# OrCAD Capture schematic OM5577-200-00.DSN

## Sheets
1 PN7120: size A4; title: .; rev: 00; note: PN7120 NFC Controller Board
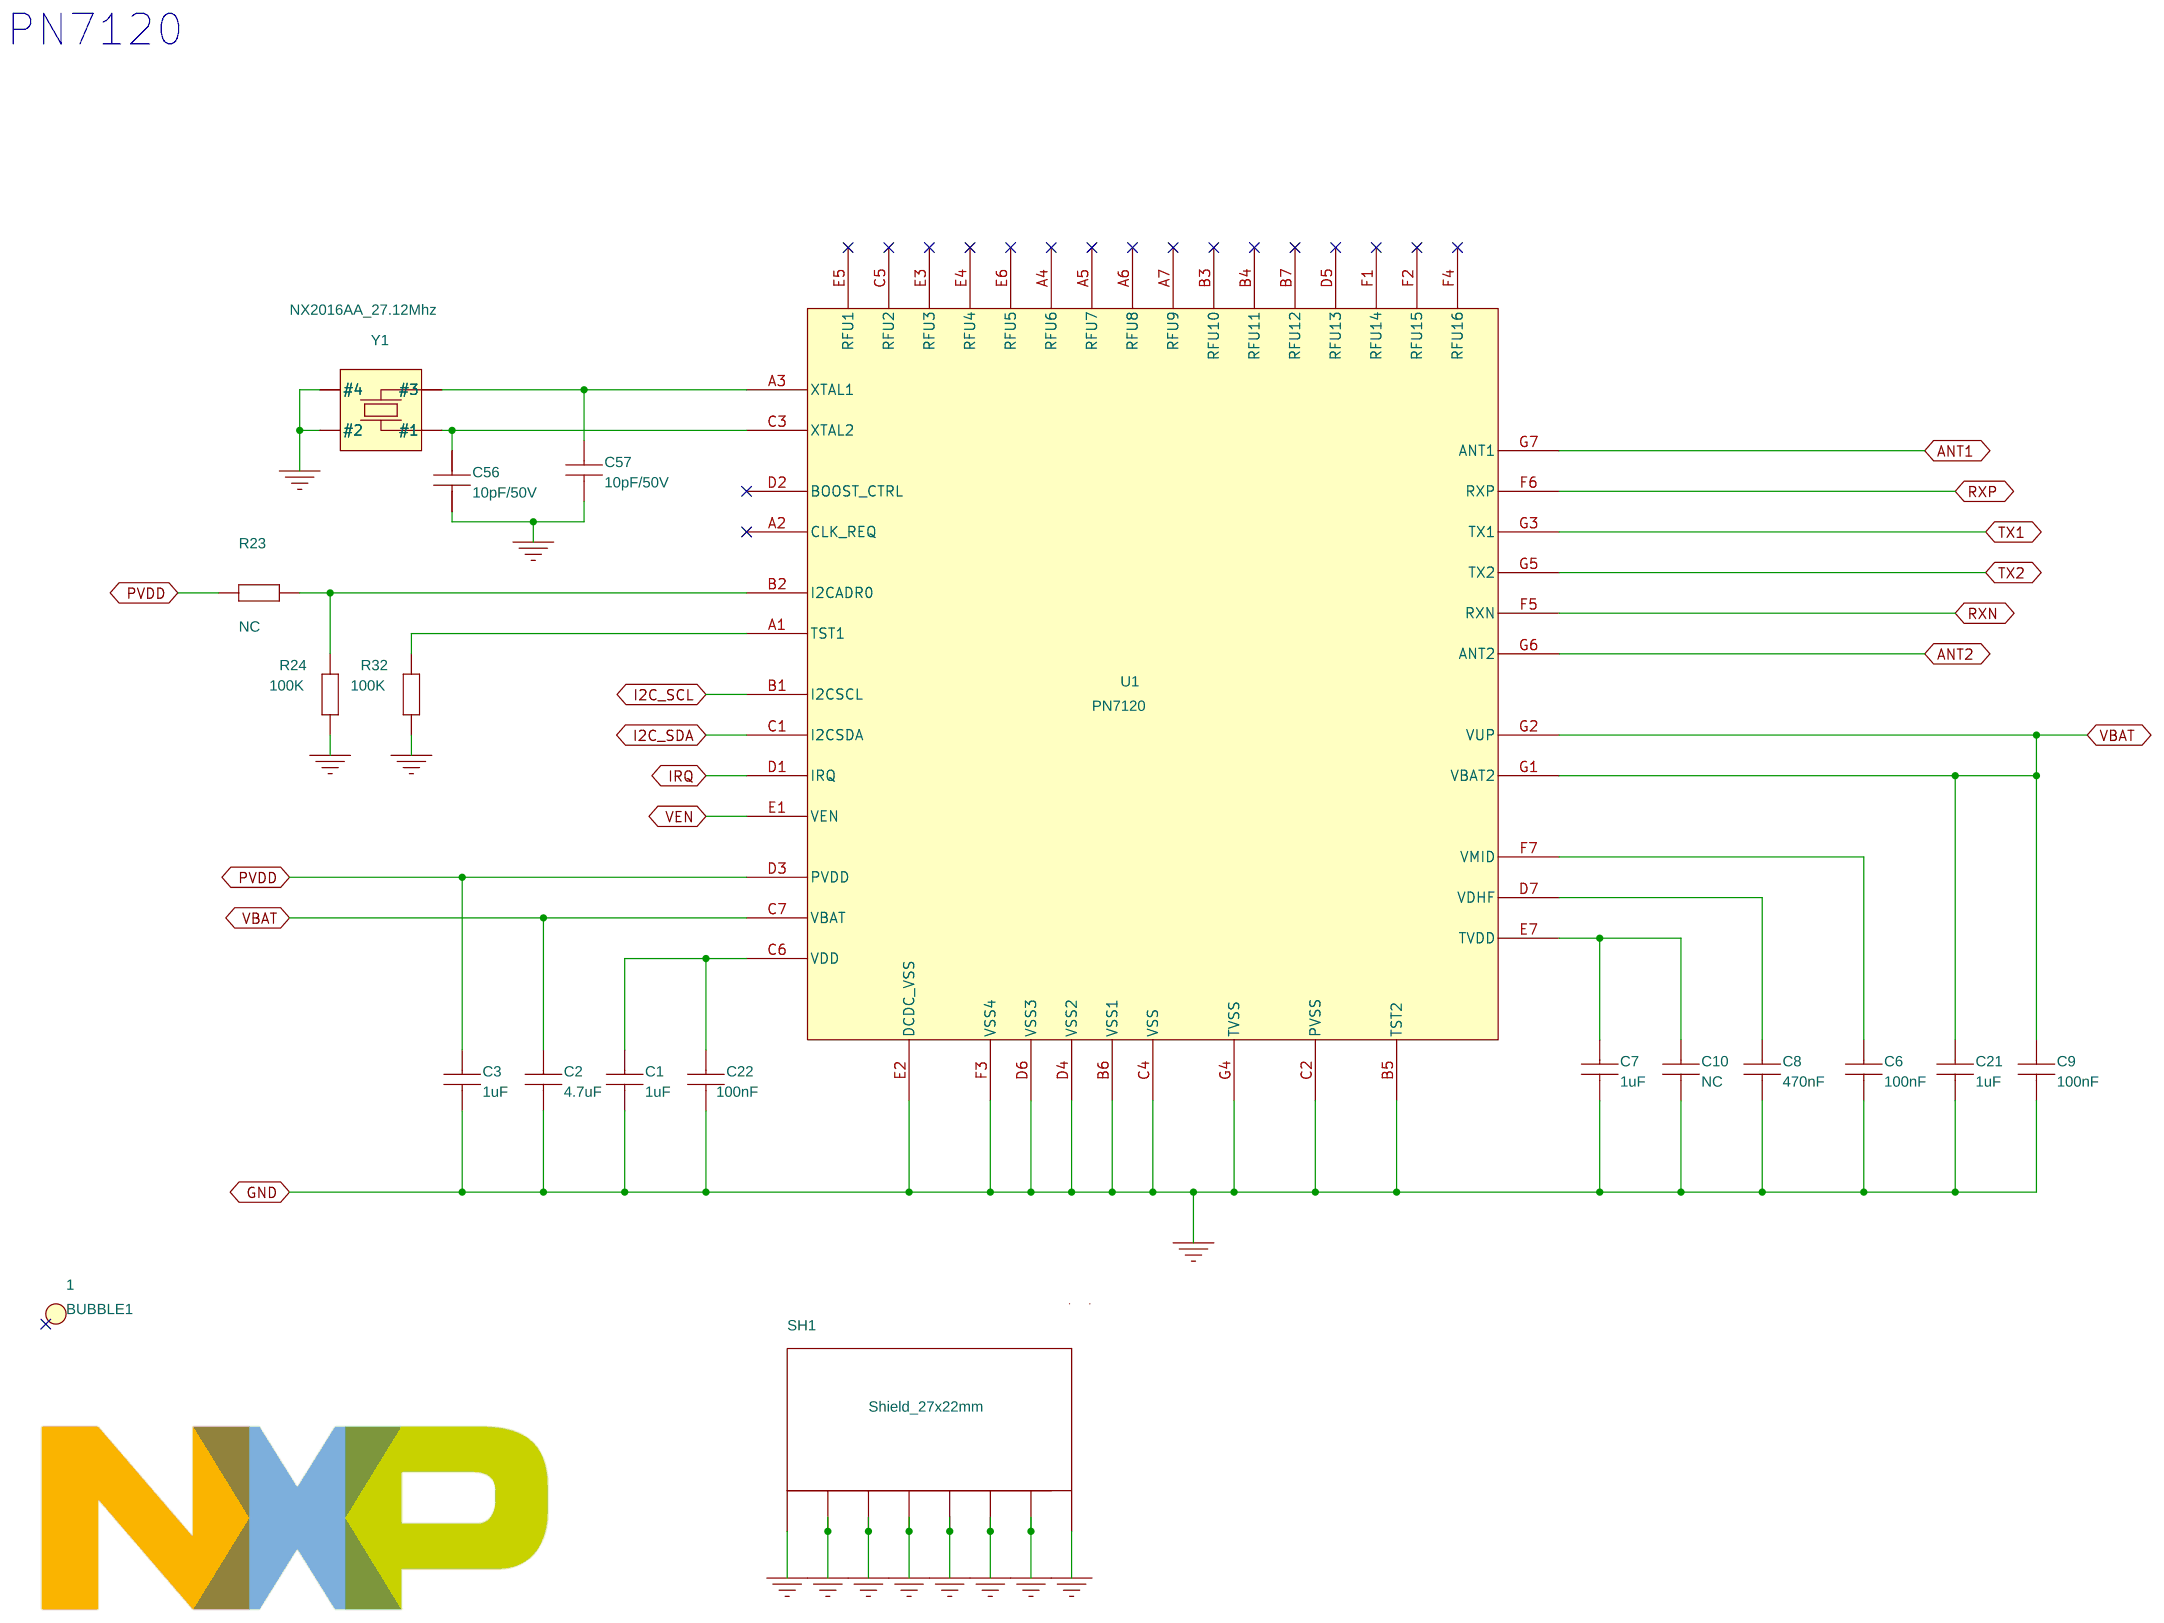
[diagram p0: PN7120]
2 RF Interface: size A4
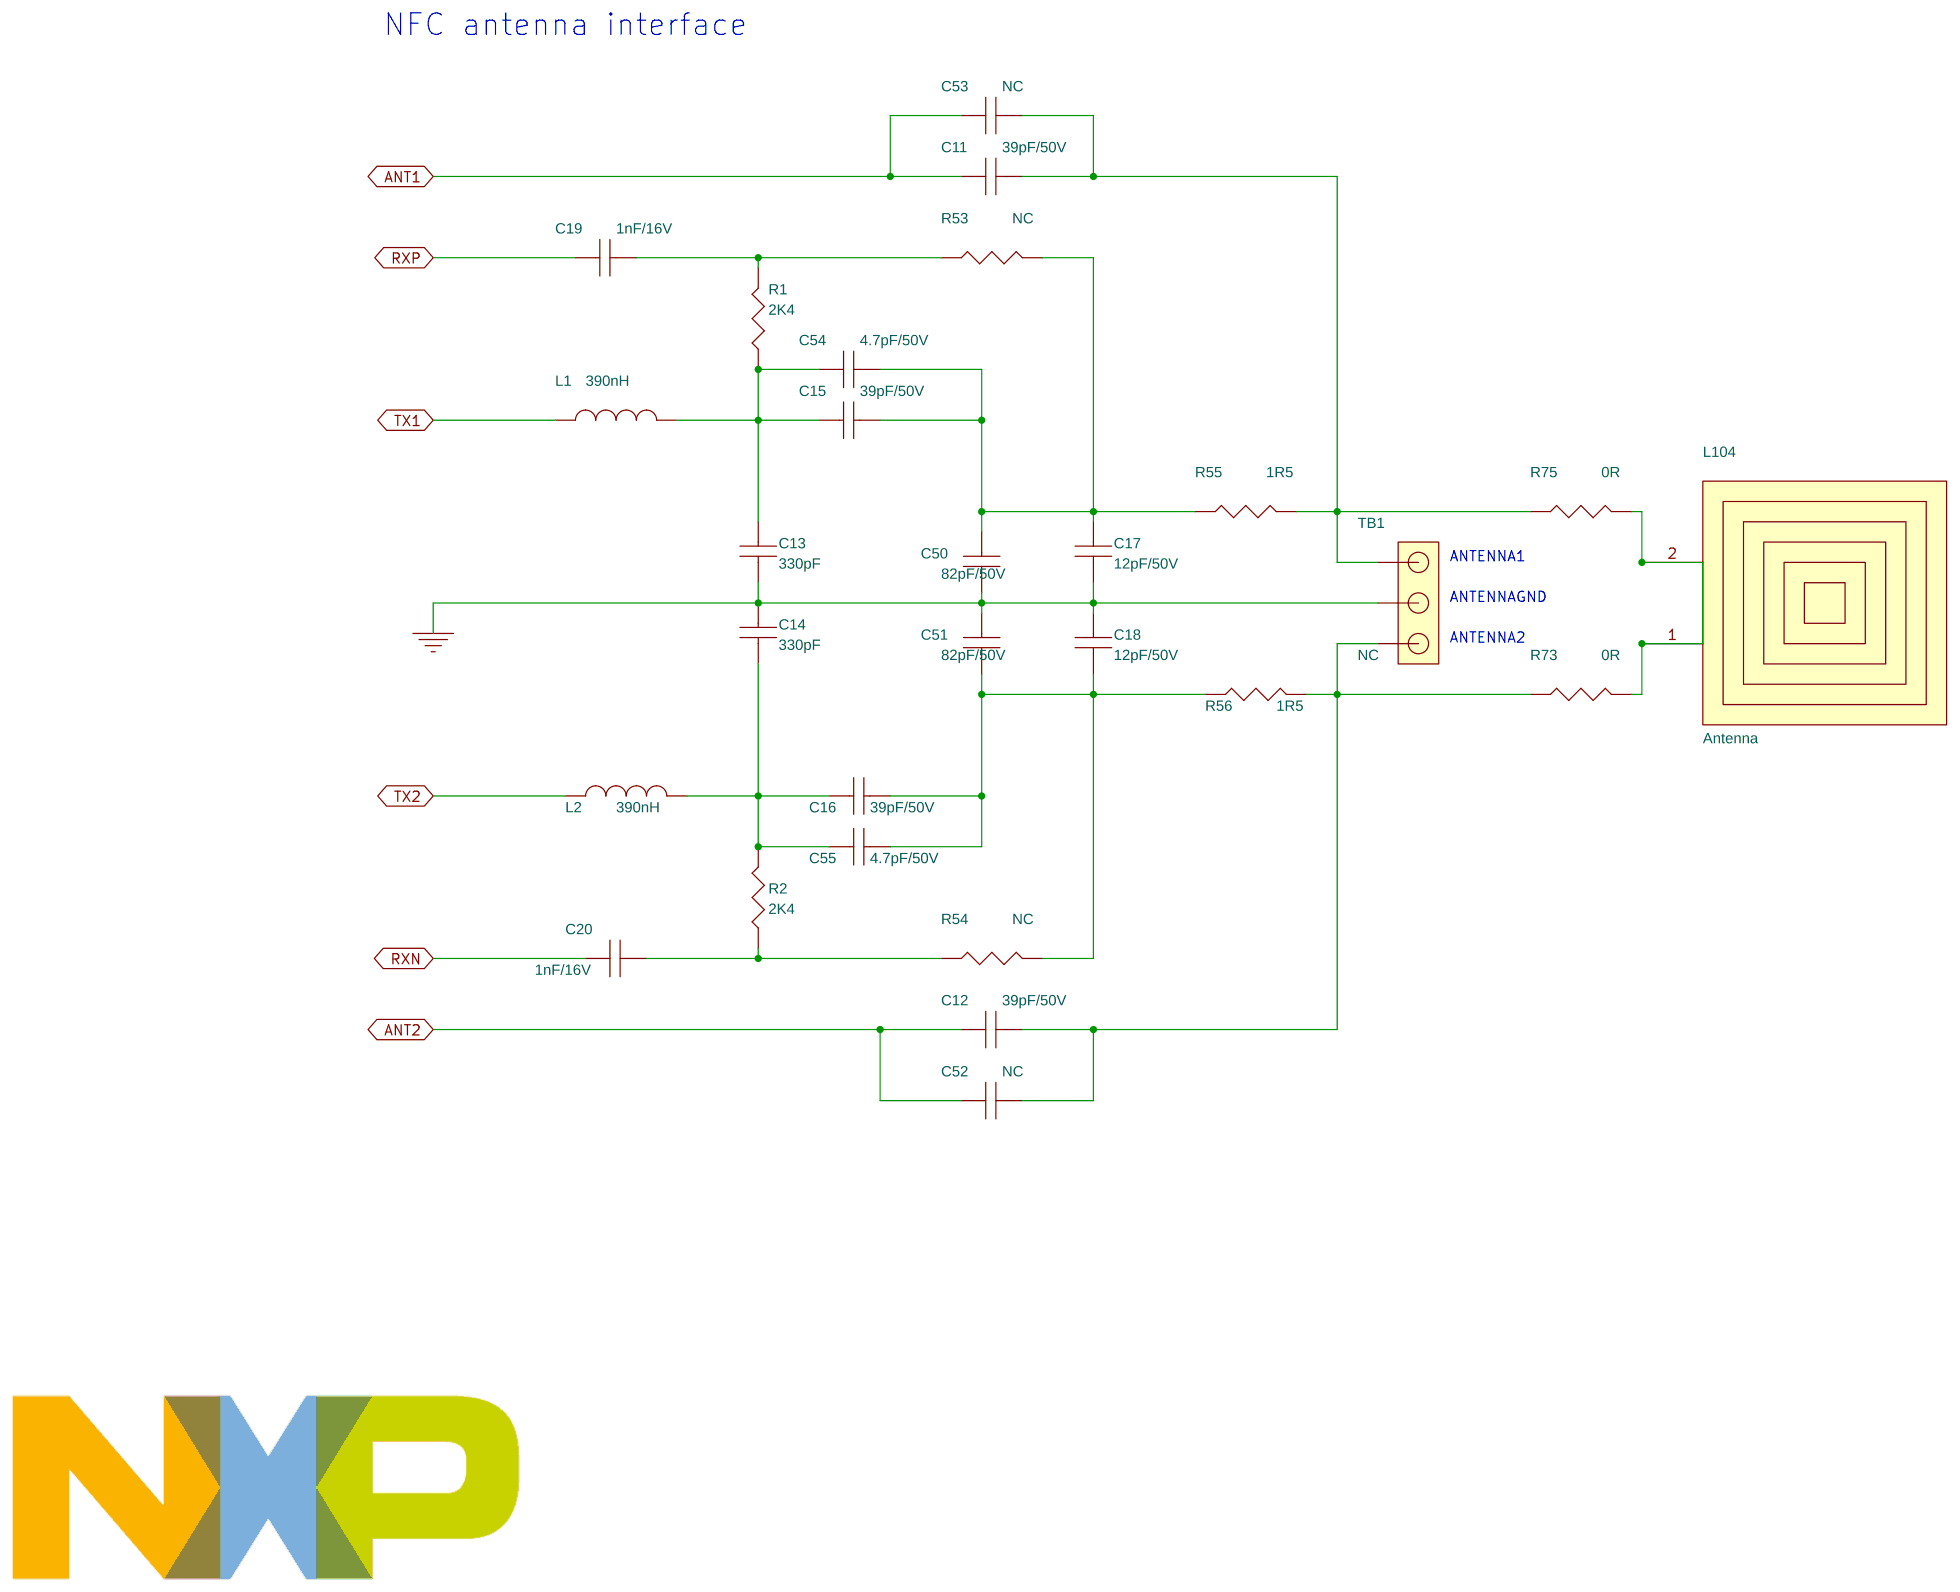
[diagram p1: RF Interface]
3 Connectors: size A4
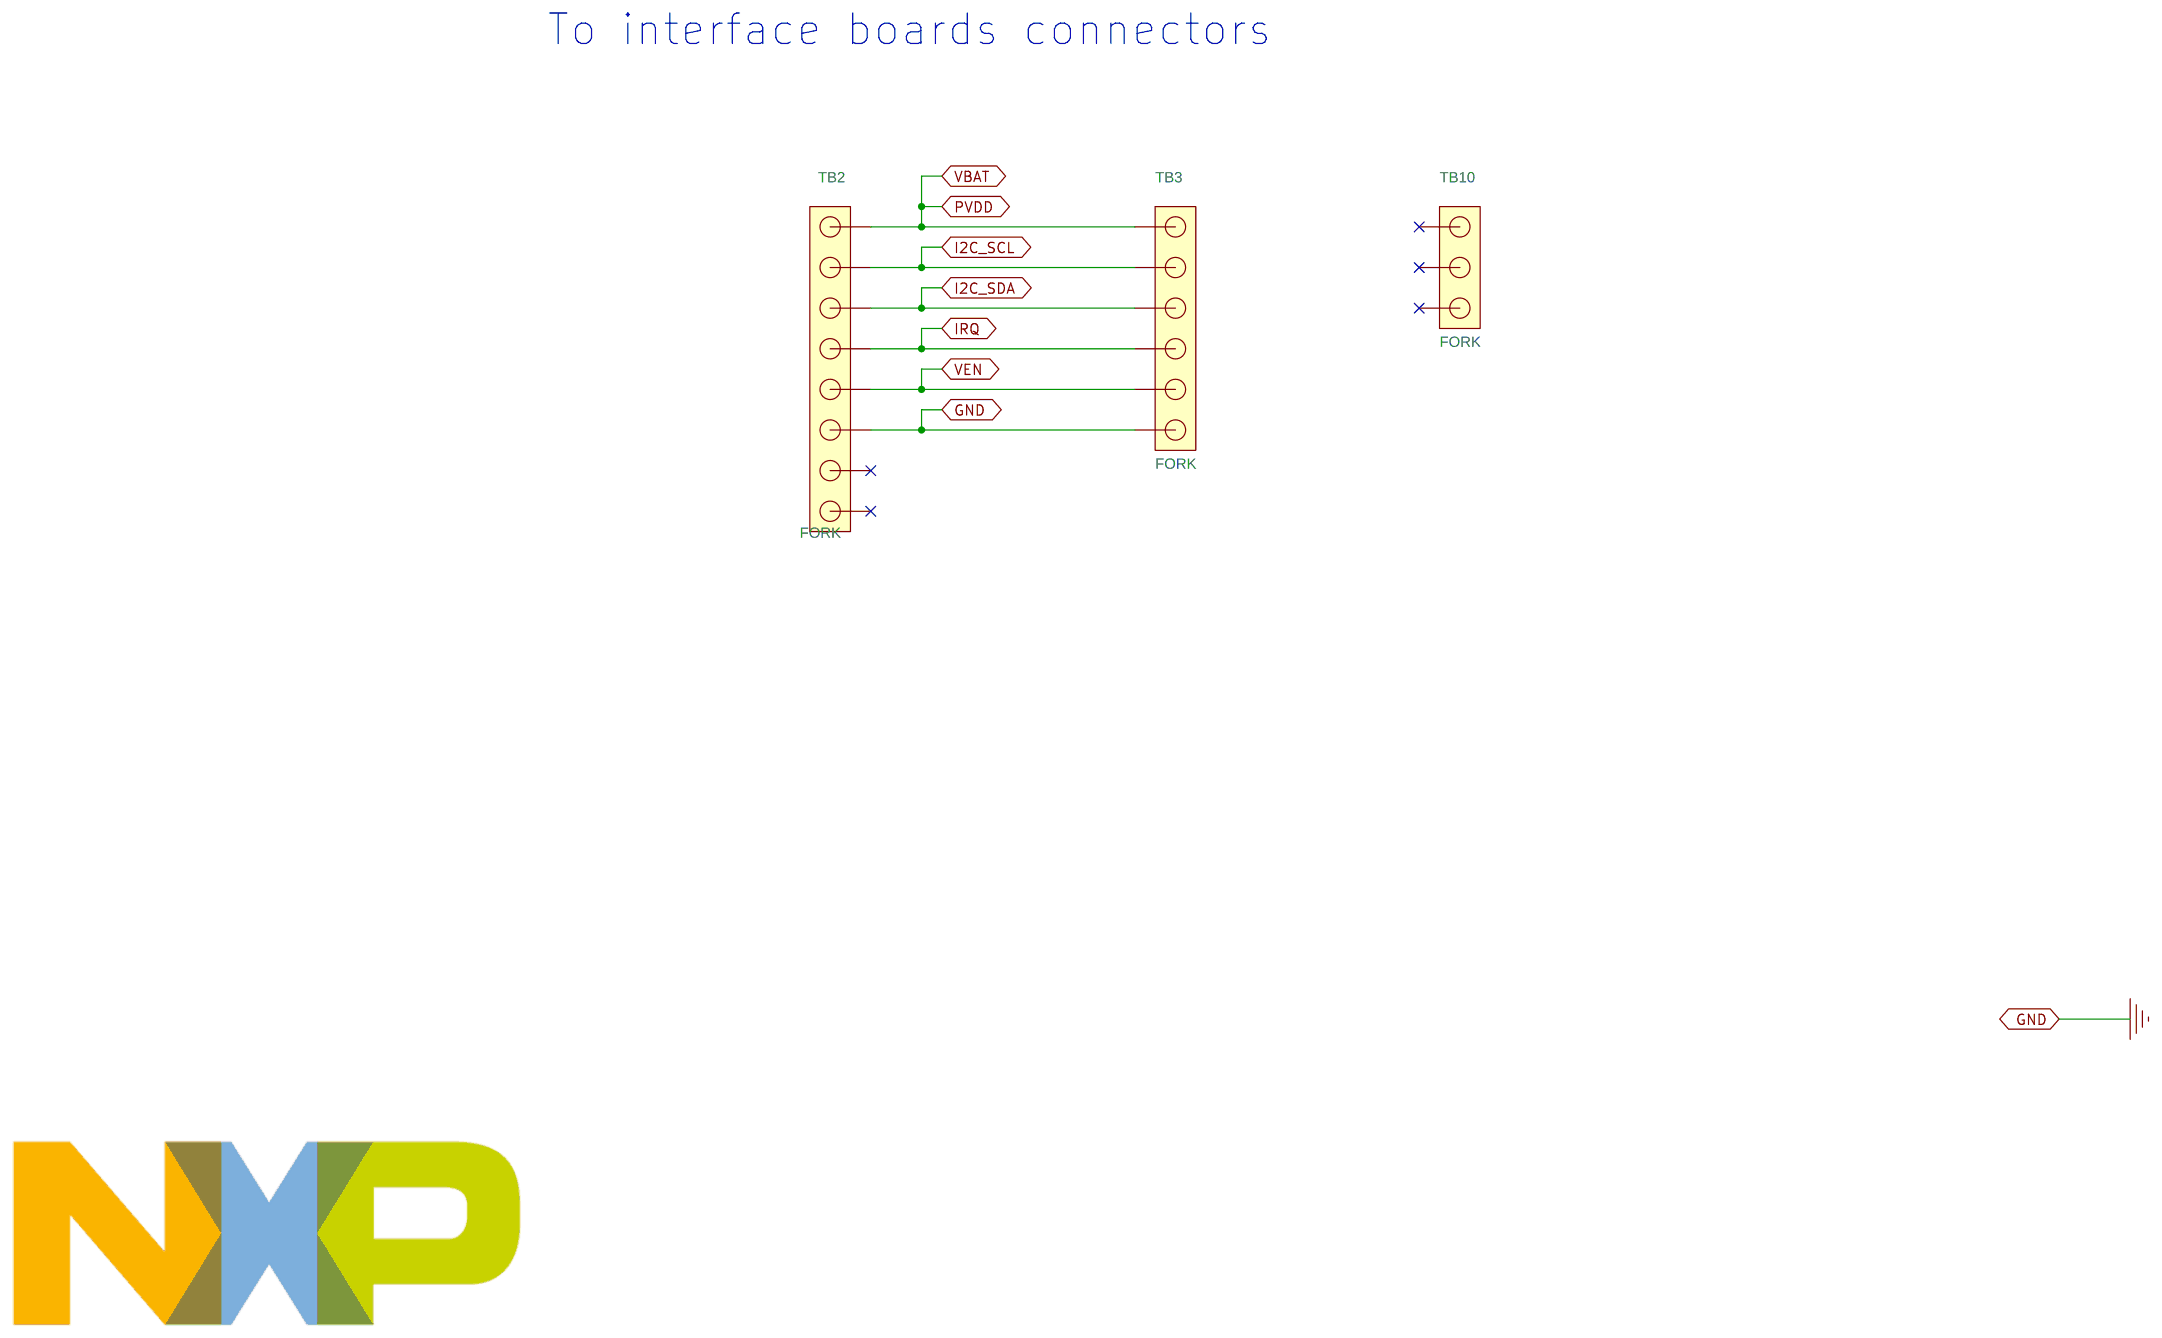
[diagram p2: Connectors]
4 BEAGLEBONE: size A4; note: BeagleBone Interface Board
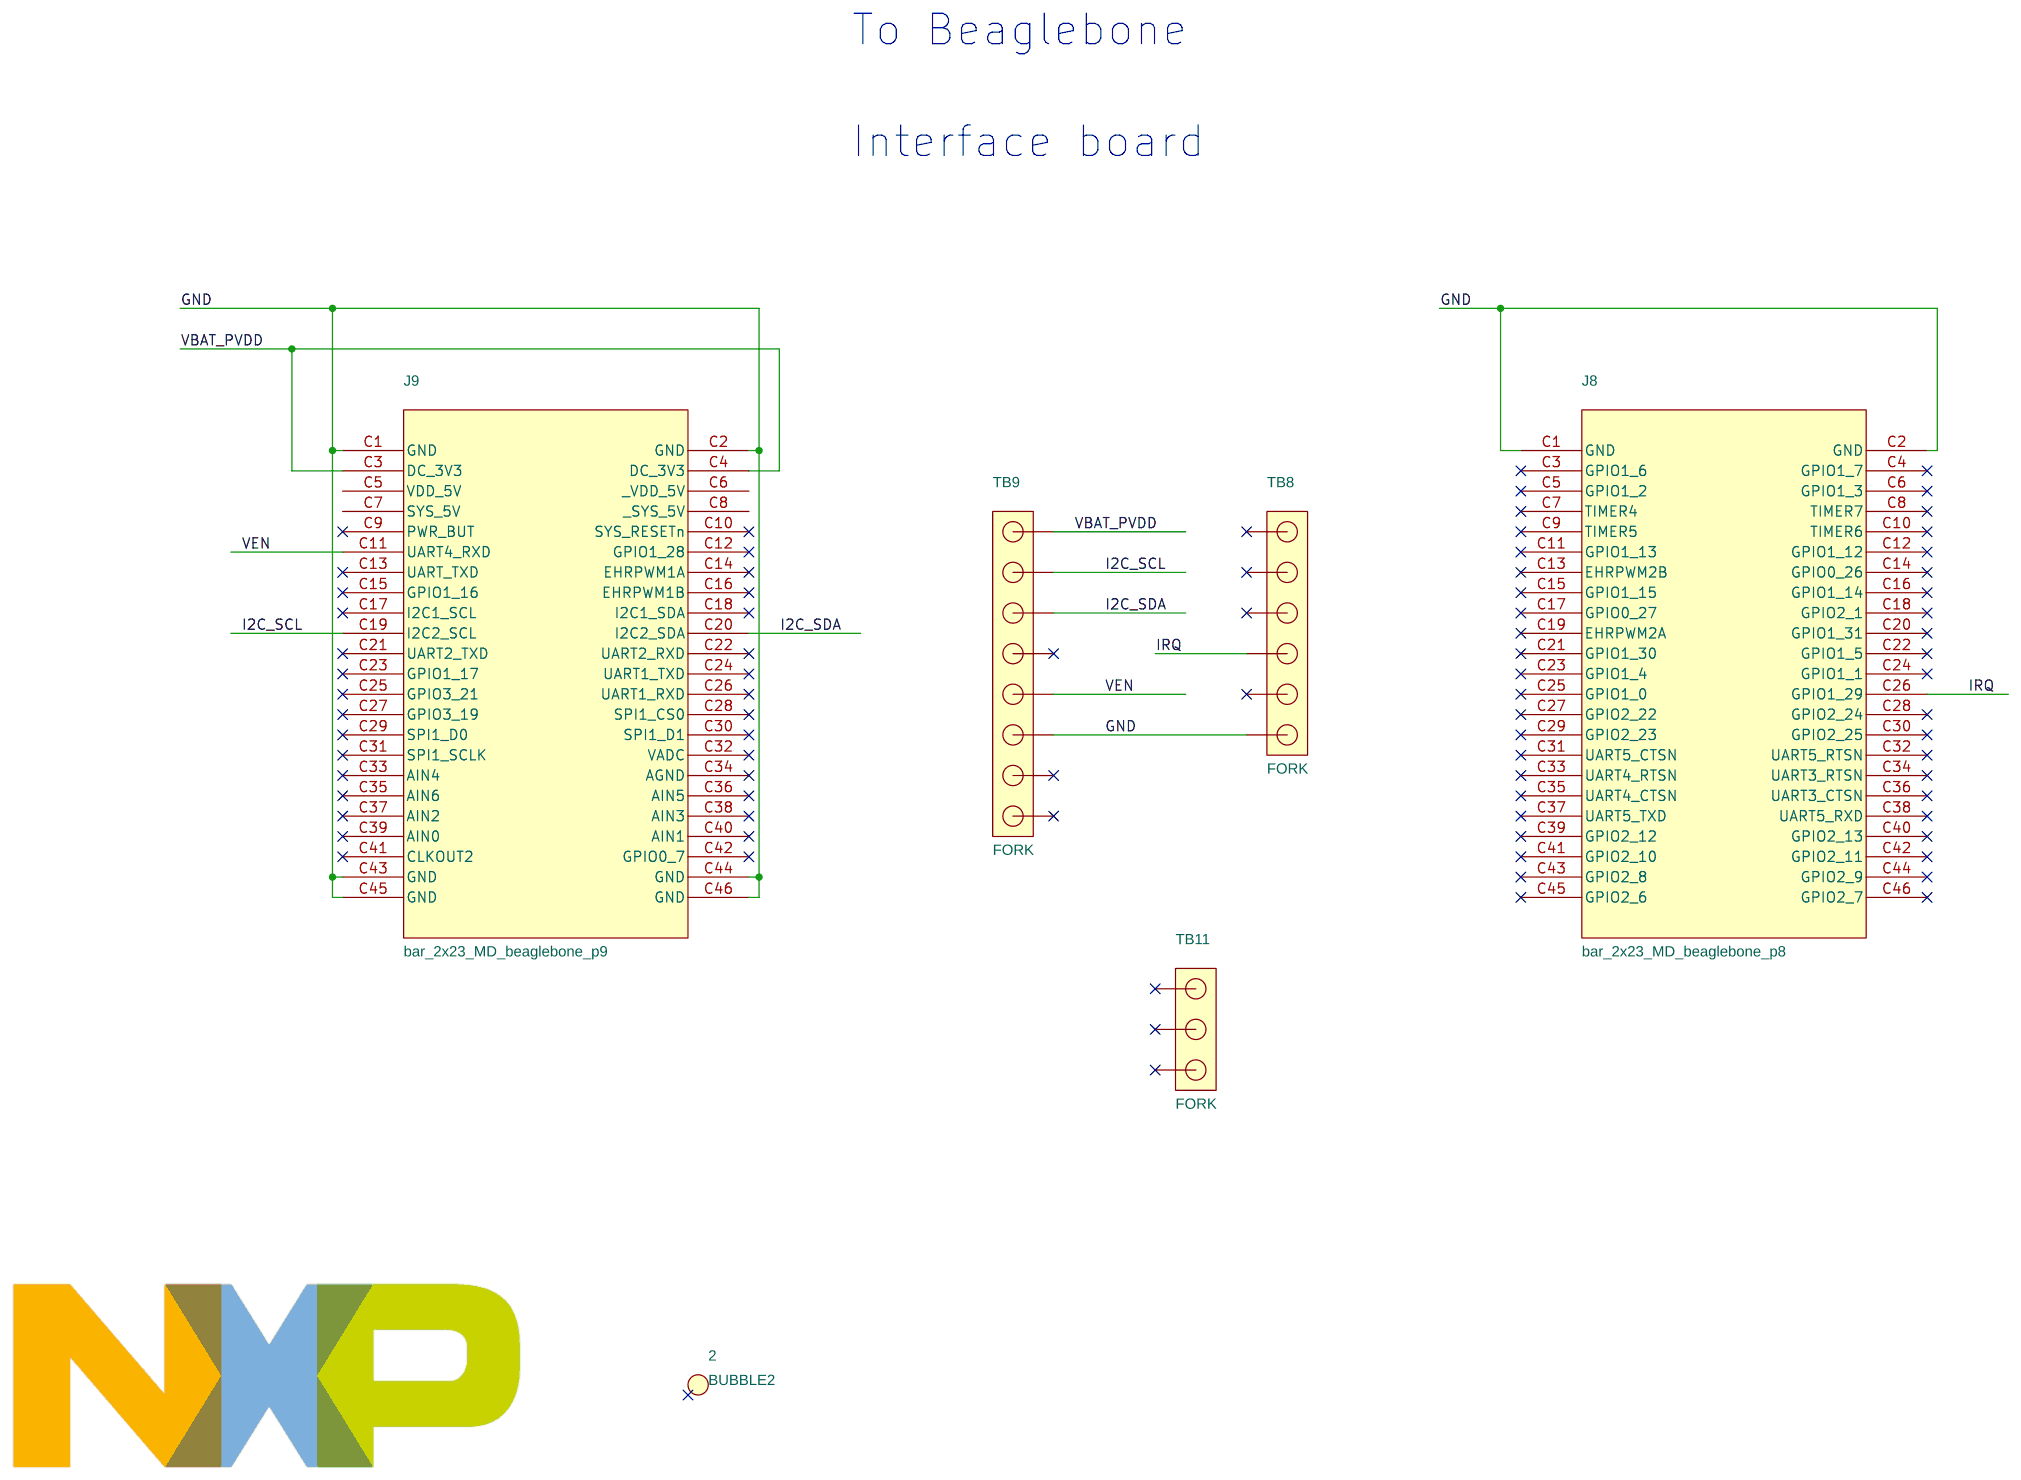
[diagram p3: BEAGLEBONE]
5 RASPBERRYPI: size A4; note: Raspberry Pi Interface Board
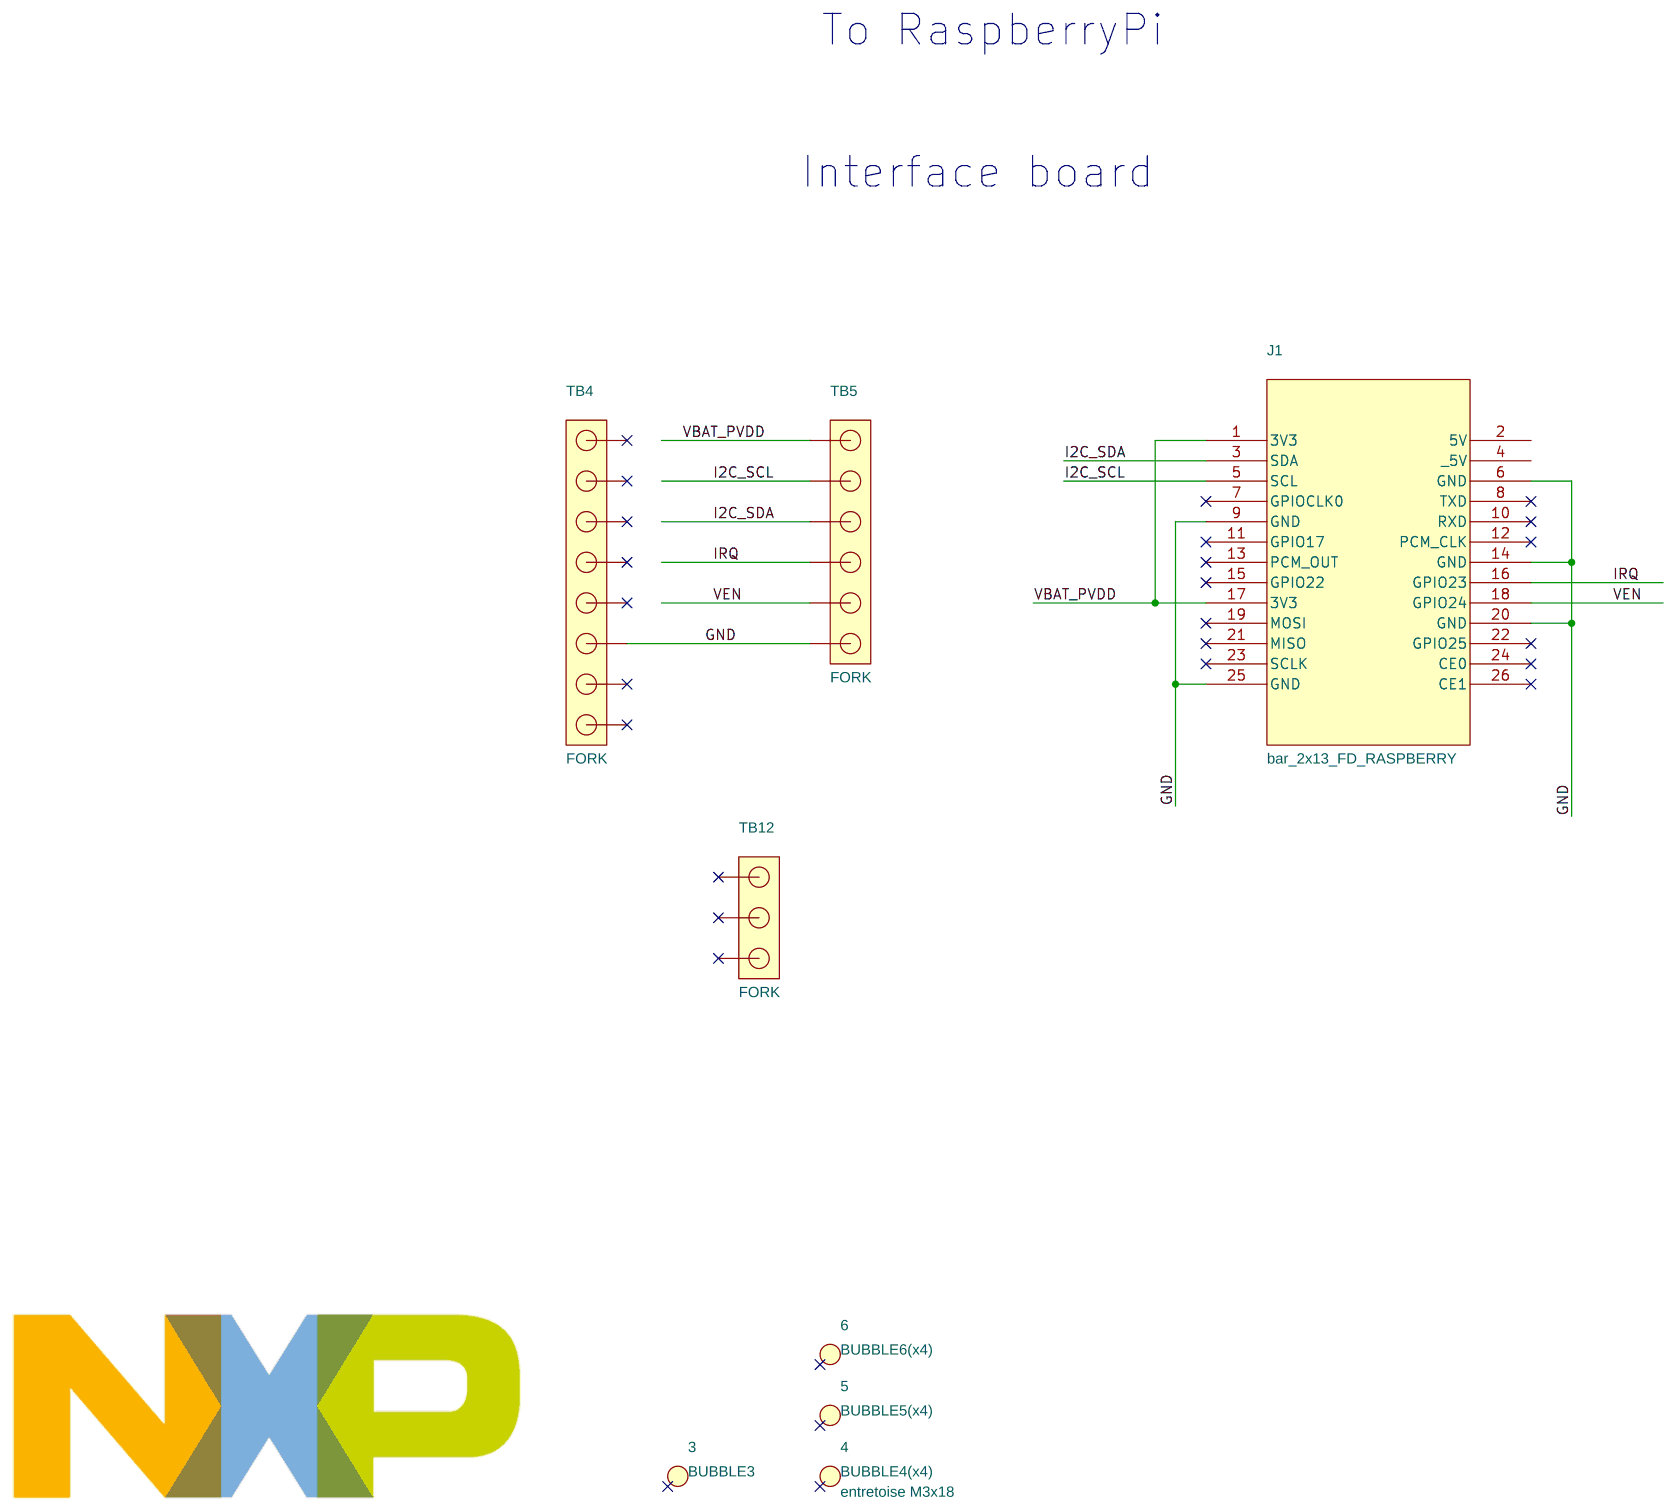
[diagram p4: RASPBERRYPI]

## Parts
sheet BEAGLEBONE
2  BUBBLE2  [BUBBLE_DIAM8]
J8  bar_2x23_MD_beaglebone_p8  [bar_2x23_spe_beaglebone]
J9  bar_2x23_MD_beaglebone_p9  [bar_2x23_spe_beaglebone]
TB8  FORK  [AGPS1-06-BSE]
TB9  FORK  [AGPS1-08-BSE]
TB11  FORK  [AGPS1-03-BSE]
sheet Connectors
TB2  FORK  [AGPS1-08-BCZ-1MM3]
TB3  FORK  [AGPS1-06-BCZ-1MM3]
TB10  FORK  [AGPS1-03-BCZ-1MM3]
sheet PN7120
1  BUBBLE1  [BUBBLE_DIAM8]
C1  1uF  [c0402]
C2  4.7uF  [c0402]
C3  1uF  [c0402]
C6  100nF  [c0402]
C7  1uF  [c0402]
C8  470nF  [c0402]
C9  100nF  [c0402]
C10  NC  [c0402]
C21  1uF  [c0402]
C22  100nF  [c0402]
C56  10pF/50V  [c0402]
C57  10pF/50V  [c0402]
R23  NC  [0402r]
R24  100K  [0402r]
R32  100K  [0402r]
SH1  Shield_27x22mm  [SHIELD_27X22]
U1  PN7120  [vfbga49_050_sot1320-1]
Y1  NX2016AA_27.12Mhz  [NX2016AA]
sheet RASPBERRYPI
3  BUBBLE3  [BUBBLE_DIAM8]
4  BUBBLE4(x4)  [BUBBLE_DIAM8]
5  BUBBLE5(x4)  [BUBBLE_DIAM8]
6  BUBBLE6(x4)  [BUBBLE_DIAM8]
J1  bar_2x13_FD_RASPBERRY  [bar_2x13_FD_spe_raspberry]
TB4  FORK  [AGPS1-08-BSE]
TB5  FORK  [AGPS1-06-BSE]
TB12  FORK  [AGPS1-03-BSE]
sheet RF Interface
C11  39pF/50V  [C0603]
C12  39pF/50V  [C0603]
C13  330pF  [C0603]
C14  330pF  [C0603]
C15  39pF/50V  [C0603]
C16  39pF/50V  [C0603]
C17  12pF/50V  [C0603]
C18  12pF/50V  [C0603]
C19  1nF/16V  [C0603]
C20  1nF/16V  [C0603]
C50  82pF/50V  [C0603]
C51  82pF/50V  [C0603]
C52  NC  [C0603]
C53  NC  [C0603]
C54  4.7pF/50V  [C0603]
C55  4.7pF/50V  [C0603]
L1  390nH  [self_0603]
L2  390nH  [self_0603]
L104  Antenna  [ANTENNA_4T_40x40]
R1  2K4  [R0603]
R2  2K4  [R0603]
R53  NC  [R0603]
R54  NC  [R0603]
R55  1R5  [R0603]
R56  1R5  [R0603]
R73  0R  [R0603]
R75  0R  [R0603]
TB1  NC  [bar_1x3_MD]

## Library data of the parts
2 = BUBBLE_CI: Designation: BeagleBone_Interface_Printed_Circuit_Board:OM5577
J8 = bar_2x23_MD_beaglebone_p8
J9 = bar_2x23_MD_beaglebone_p9_1
TB5 TB8 = bar_1x6_MD: Designation: Remove Header after soldering; Manufacturer: ANTELEC
TB4 TB9 = bar_1x8_MD: Designation: Remove Header after soldering; Manufacturer: ANTELEC
TB11 TB12 = bar_1x3_MD: Designation: Remove Header after soldering; Manufacturer: ANTELEC
TB2 = bar_1x8_MD: Designation: Remove Header after soldering; Manufacturer: ANTELEC; ref. manufacturer: AGPS1-08-BCZ-1.3
TB3 = bar_1x6_MD: Designation: Remove Header after soldering; Manufacturer: ANTELEC; ref. manufacturer: AGPS1-06-BCZ-1.3
TB10 = bar_1x3_MD: Designation: Remove Header after soldering; Manufacturer: ANTELEC; ref. manufacturer: AGPS1-03-BCZ-1.3
1 = BUBBLE_CI: Designation: PN7120_NFC_Controller_Printed_Circuit_Board:OM5577
C1 C3 C7 C21 = CAP_NP: Designation: Capacitor, 6.3V, 20%, X5R; Manufacturer: MURATA
C2 = CAP_NP: Designation: Capacitor, 6.3V, X5R; Manufacturer: TDK; REF.Manufacturer: C1005X5R0J475T
C6 C9 C22 = CAP_NP: Designation: Capacitor,CER2,0402,X7R,16V,10%; Manufacturer: MURATA
C8 = CAP_NP: Designation: Capacitor,CER2,0402,X5R,16V,10%
C10 C52 C53 = CAP_NP: Designation: !!!NOT CONNECTED !!!
C56 C57 = CAP_NP: Designation: Capacitor,CER2,0402,C0G,50V,2%; Manufacturer: MURATA
R23 = RESISTOR_0: DESIGNATION: !!!NOT CONNECTED !!!
R24 R32 = RESISTOR_0: DESIGNATION: Resistor,Package:0402,1%,1/16W
SH1 = OM5782_Shield_1: SHIELD_27X22_23-CBS; Observations: Fournit par NXP; Référence Fournisseur: ...
U1 = PN7120_VFBGA49
Y1 = NX2016AA_xMhz: Manufacturer: NDK
3 = BUBBLE_CI: Designation: Raspberry Pi_Interface_Printed_Circuit_Board:OM5577
4 = BUBBLE_entretoise_nylon_M3x20: Designation: SKIFFY:300_3180_000_38_Spacer_Nylon_Female/Female_M3x18; TYPE: entretoise M3x18
5 = BUBBLE_RONDELLE_M3_PLATE
6 = BUBBLE_VIS_M3X6
J1 = bar_2x13_FD_RASPBERRY_0
C11-C16 C50 C51 = CAP_NP: Designation: Capacitor,CER2,0603,C0G,50V,5%
C17 C18 = CAP_NP: Designation: Capacitor,CER2,0603,C0G,50V,2%
C19 C20 = CAP_NP: Designation: Capacitor,CER2,0603,X7R,16V,10%
C54 C55 = CAP_NP: Designation: Capacitor,CER2,0402,C0G,50V,2%
L1 L2 = INDUCTOR: Designation: Chip,inductor,SMD,5%,0603; Manufacturer: TDK; REF.Manufacturer: LQW18ANR39J00
L104 = Antenna: Designation: ***PRINTED BOARD***
R1 R2 R55 R56 R73 R75 = RESISTOR: Designation: Resistor,Package:0603,1%,1/16W
R53 R54 = RESISTOR: Designation: !!!NOT CONNECTED !!!
TB1 = bar_1x3_MD: Designation: !!!NOT CONNECTED !!!

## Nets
5V: J1.2(5V)
GND: C1.2 C2.2 C3.2 C6.2 C7.2 C8.2 C9.2 C10.2 C13.2 C14.1 C17.2 C18.1 C21.2 C22.2 C50.2 C51.1 C56.2 C57.2 R24.1 R32.1 SH1.1 SH1.2 SH1.3 SH1.4 SH1.5 SH1.6 SH1.7 SH1.8 TB1.2 TB2.6 TB3.6 U1.B5(TST2) U1.B6(VSS1) U1.C2(PVSS) U1.C4(VSS) U1.D4(VSS2) U1.D6(VSS3) U1.E2(DCDC_VSS) U1.F3(VSS4) U1.G4(TVSS) Y1.2(#2) Y1.4(#4)
GND (page 4-BEAGLEBONE): J8.C1(GND) J8.C2(GND) J9.C1(GND) J9.C2(GND) J9.C43(GND) J9.C44(GND) J9.C45(GND) J9.C46(GND) TB8.6 TB9.6
GND (page 5-RASPBERRYPI): J1.6(GND) J1.9(GND) J1.14(GND) J1.20(GND) J1.25(GND) TB4.6 TB5.6
PVDD: C2.1 C3.1 C9.1 C21.1 R23.2 TB2.1 TB3.1 U1.C7(VBAT) U1.D3(PVDD) U1.G1(VBAT2) U1.G2(VUP)
VBAT_PVDD: J9.C3(DC_3V3) J9.C4(DC_3V3) TB9.1
VBAT_PVDD (page 5-RASPBERRYPI): J1.1(3V3) J1.17(3V3) TB5.1
VDD_5V: J9.C5(VDD_5V)
_5V: J1.4(_5V)
_SYS_5V: J9.C8(_SYS_5V)
_VDD_5V: J9.C6(_VDD_5V)
ANT1: C11.1 C53.1 U1.G7(ANT1)
ANT2: C12.1 C52.1 U1.G6(ANT2)
I2C_SCL: TB2.2 TB3.2 U1.B1(I2CSCL)
I2C_SCL (page 4-BEAGLEBONE): J9.C19(I2C2_SCL) TB9.2
I2C_SCL (page 5-RASPBERRYPI): J1.5(SCL) TB5.2
I2C_SDA: TB2.3 TB3.3 U1.C1(I2CSDA)
I2C_SDA (page 4-BEAGLEBONE): J9.C20(I2C2_SDA) TB9.3
I2C_SDA (page 5-RASPBERRYPI): J1.3(SDA) TB5.3
IRQ: TB2.4 TB3.4 U1.D1(IRQ)
IRQ (page 4-BEAGLEBONE): J8.C26(GPIO1_29) TB8.4
IRQ (page 5-RASPBERRYPI): J1.16(GPIO23) TB5.4
RXN: C20.1 U1.F5(RXN)
RXP: C19.1 U1.F6(RXP)
SYS_5V: J9.C7(SYS_5V)
TX1: L1.1 U1.G3(TX1)
TX2: L2.1 U1.G5(TX2)
VEN: TB2.5 TB3.5 U1.E1(VEN)
VEN (page 4-BEAGLEBONE): J9.C11(UART4_RXD) TB9.5
VEN (page 5-RASPBERRYPI): J1.18(GPIO24) TB5.5
N2189999: C15.2 C17.1 C50.1 C54.2 R53.2 R55.1
N2190055: C16.2 C18.2 C51.2 C55.2 R54.2 R56.1
N2190079: C13.1 C15.1 C54.1 L1.2 R1.1
N2190159: C12.2 C52.2 R56.2 R73.1 TB1.3
N2190199: C11.2 C53.2 R55.2 R75.1 TB1.1
N2190513: C14.2 C16.1 C55.1 L2.2 R2.2
N2190991: L104.1 L104.2 R73.2 R75.2
N2198580: R23.1 R24.2 U1.B2(I2CADR0)
N2222470: C20.2 R2.1 R54.1
N2227379: C19.2 R1.2 R53.1
N2256986: C57.1 U1.A3(XTAL1) Y1.3(#3)
N2256988: C56.1 U1.C3(XTAL2) Y1.1(#1)
N2257197: R32.2 U1.A1(TST1)
N2257995: C1.1 C22.1 U1.C6(VDD)
N2259746: C7.1 C10.1 U1.E7(TVDD)
N2259753: C8.1 U1.D7(VDHF)
N2259760: C6.1 U1.F7(VMID)

Not connected (* = marked no-connect by the designer): 1 1*; 2 1*; 3 1*; 4 1*; 5 1*; 6 1*; J1 7(GPIOCLK0)* 8(TXD)* 10(RXD)* 11(GPIO17)* 12(PCM_CLK)* 13(PCM_OUT)* 15(GPIO22)* 19(MOSI)* 21(MISO)* 22(GPIO25)* 23(SCLK)* 24(CE0)* 26(CE1)*; J8 C3(GPIO1_6)* C4(GPIO1_7)* C5(GPIO1_2)* C6(GPIO1_3)* C7(TIMER4)* C8(TIMER7)* C9(TIMER5)* C10(TIMER6)* C11(GPIO1_13)* C12(GPIO1_12)* C13(EHRPWM2B)* C14(GPIO0_26)* C15(GPIO1_15)* C16(GPIO1_14)* C17(GPIO0_27)* C18(GPIO2_1)* C19(EHRPWM2A)* C20(GPIO1_31)* C21(GPIO1_30)* C22(GPIO1_5)* C23(GPIO1_4)* C24(GPIO1_1)* C25(GPIO1_0)* C27(GPIO2_22)* C28(GPIO2_24)* C29(GPIO2_23)* C30(GPIO2_25)* C31(UART5_CTSN)* C32(UART5_RTSN)* C33(UART4_RTSN)* C34(UART3_RTSN)* C35(UART4_CTSN)* C36(UART3_CTSN)* C37(UART5_TXD)* C38(UART5_RXD)* C39(GPIO2_12)* C40(GPIO2_13)* C41(GPIO2_10)* C42(GPIO2_11)* C43(GPIO2_8)* C44(GPIO2_9)* C45(GPIO2_6)* C46(GPIO2_7)*; J9 C9(PWR_BUT)* C10(SYS_RESETn)* C12(GPIO1_28)* C13(UART_TXD)* C14(EHRPWM1A)* C15(GPIO1_16)* C16(EHRPWM1B)* C17(I2C1_SCL)* C18(I2C1_SDA)* C21(UART2_TXD)* C22(UART2_RXD)* C23(GPIO1_17)* C24(UART1_TXD)* C25(GPIO3_21)* C26(UART1_RXD)* C27(GPIO3_19)* C28(SPI1_CS0)* C29(SPI1_D0)* C30(SPI1_D1)* C31(SPI1_SCLK)* C32(VADC)* C33(AIN4)* C34(AGND)* C35(AIN6)* C36(AIN5)* C37(AIN2)* C38(AIN3)* C39(AIN0)* C40(AIN1)* C41(CLKOUT2)* C42(GPIO0_7)*; TB2 7* 8*; TB4 1* 2* 3* 4* 5* 7* 8*; TB8 1* 2* 3* 5*; TB9 4* 7* 8*; TB10 1* 2* 3*; TB11 1* 2* 3*; TB12 1* 2* 3*; U1 A2(CLK_REQ)* A4(RFU6)* A5(RFU7)* A6(RFU8)* A7(RFU9)* B3(RFU10)* B4(RFU11)* B7(RFU12)* C5(RFU2)* D2(BOOST_CTRL)* D5(RFU13)* E3(RFU3)* E4(RFU4)* E5(RFU1)* E6(RFU5)* F1(RFU14)* F2(RFU15)* F4(RFU16)*

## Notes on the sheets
sheet 1
- PN7120
sheet 2
- NFC antenna interface
- ANTENNA1
- ANTENNAGND
- ANTENNA2
sheet 3
- To interface boards connectors
sheet 4
- To Beaglebone
- Interface board
sheet 5
- To RaspberryPi
- Interface board
